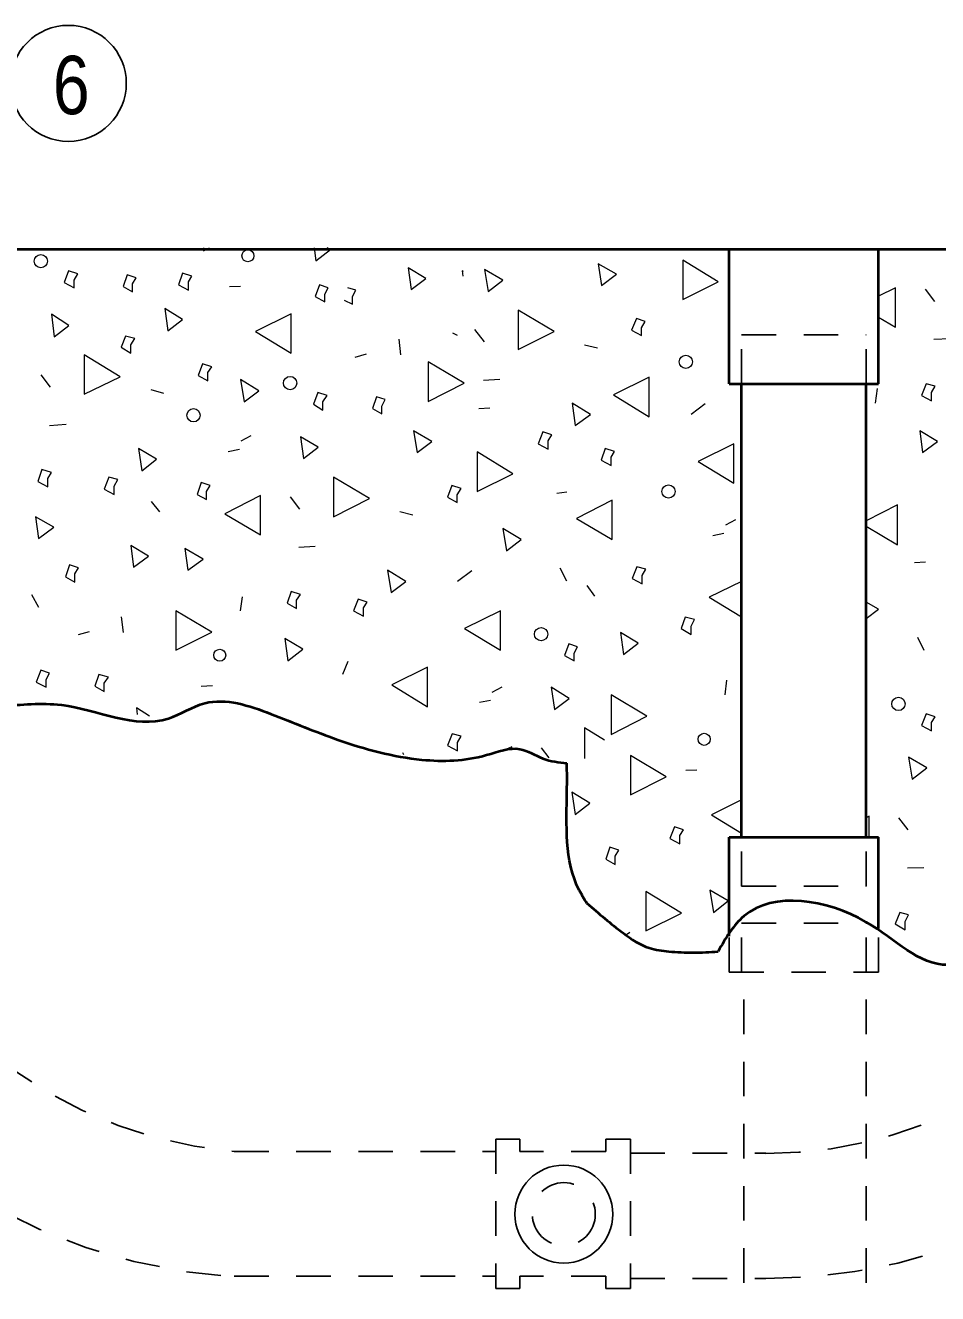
# Model space of a CAD drawing. Extents: x 312583 to 312854, y 144419 to 144597.
# Drawn here: x 312733.6 to 312745.49, y 144531.37 to 144547.9 of the extents above; entities that cross this region are included whole.
import ezdxf

# ---------------------------------------------------------------- set-up
doc = ezdxf.new("R2010")
doc.units = 0
doc.header["$LTSCALE"] = 0.3
doc.linetypes.add('SHORT_DASHED', pattern=[2.7, 1.5, -1.2])
doc.layers.add('1', color=7, linetype='Continuous', lineweight=25)
doc.layers.add('2', color=7, linetype='Continuous', lineweight=13)

msp = doc.modelspace()

# ---------------------------------------------------------------- linework, layer by layer
at = {"layer": '1', "lineweight": 40}
for p, q in [((312722.2688, 144544.9833), (312760.6021, 144544.9833)), ((312742.7771, 144543.2276), (312742.7771, 144544.9833)), ((312744.7245, 144543.2276), (312744.7245, 144544.9833)), ((312742.7771, 144543.2276), (312744.7245, 144543.2276)), ((312742.9381, 144537.3166), (312742.9381, 144543.2276)), ((312744.5635, 144537.3166), (312744.5635, 144543.2276)), ((312742.7771, 144537.3166), (312744.7245, 144537.3166)), ((312742.7771, 144536.0286), (312742.7771, 144537.3166)), ((312744.7245, 144536.1283), (312744.7245, 144537.3166))]:
    msp.add_line(p, q, dxfattribs=at)
at = {"layer": '1', "linetype": 'SHORT_DASHED'}
for p, q in [((312742.9381, 144543.8639), (312744.5635, 144543.8639)), ((312742.9381, 144543.2276), (312742.9381, 144543.8639)), ((312744.5635, 144543.2276), (312744.5635, 144543.8639)), ((312742.9381, 144536.6803), (312742.9381, 144537.3166)), ((312744.5635, 144536.6803), (312744.5635, 144537.3166)), ((312742.9381, 144536.6803), (312744.5635, 144536.6803)), ((312742.9381, 144536.1973), (312744.5635, 144536.1973)), ((312742.9381, 144535.5609), (312742.9381, 144536.1973)), ((312744.5635, 144535.5609), (312744.5635, 144536.1973)), ((312744.7245, 144535.5609), (312744.7245, 144536.1283)), ((312742.7771, 144535.5609), (312742.7771, 144536.0286)), ((312742.7771, 144535.5609), (312744.7245, 144535.5609)), ((312742.9688, 144524.2219), (312742.9688, 144535.5609)), ((312744.5635, 144524.2219), (312744.5635, 144535.5609)), ((312739.7335, 144533.3836), (312739.7335, 144531.4363)), ((312739.7335, 144533.3836), (312740.0478, 144533.3836)), ((312740.0478, 144533.3836), (312740.0478, 144533.2226)), ((312741.1671, 144533.3836), (312741.1671, 144533.2226)), ((312741.1671, 144533.3836), (312741.4891, 144533.3836)), ((312741.4891, 144533.3836), (312741.4891, 144531.4363)), ((312736.3218, 144533.2226), (312739.7335, 144533.2226)), ((312741.1671, 144533.2226), (312740.0478, 144533.2226)), ((312741.4891, 144533.1996), (312743.2525, 144533.1996)), ((312736.3218, 144531.5973), (312739.7335, 144531.5973)), ((312740.0478, 144531.4363), (312740.0478, 144531.5973)), ((312741.1671, 144531.5973), (312740.0478, 144531.5973)), ((312741.1671, 144531.4363), (312741.1671, 144531.5973)), ((312741.4891, 144531.5666), (312743.2525, 144531.5666)), ((312739.7335, 144531.4363), (312740.0478, 144531.4363)), ((312741.1671, 144531.4363), (312741.4891, 144531.4363))]:
    msp.add_line(p, q, dxfattribs=at)
at = {"layer": '1'}
msp.add_circle((312740.6202, 144532.4061), 0.6389, dxfattribs=at)
at = {"layer": '1', "linetype": 'SHORT_DASHED'}
msp.add_circle((312740.6202, 144532.4061), 0.4108, dxfattribs=at)
for centre, radius, start, end in [((312736.8038, 144538.9545), 5.75, 184.14986, 265.21724), ((312736.7767, 144538.9543), 7.3792, 186.13, 266.47596), ((312743.2557, 144538.9458), 5.75, 270, 336.76867), ((312743.2557, 144538.9458), 7.3792, 270, 340.7336)]:
    msp.add_arc(centre, radius, start, end, dxfattribs=at)
at = {"layer": '1', "lineweight": 40}
for points in [[(312755.0745, 144544.9833), (312755.5728, 144544.1169), (312756.1785, 144543.2276), (312755.8258, 144542.1543), (312755.2585, 144541.7173), (312755.0055, 144540.7973), (312754.8828, 144538.5893), (312754.3461, 144537.5159), (312754.1851, 144537.3243), (312753.2728, 144536.5346), (312752.7131, 144536.7646), (312751.8468, 144536.6649), (312751.0801, 144536.7263), (312750.2215, 144536.5116), (312749.1635, 144536.4733), (312748.5425, 144536.6803), (312747.8065, 144536.3813), (312747.7145, 144536.2816), (312747.0091, 144536.3889), (312745.9128, 144535.7143), (312745.6291, 144535.6529), (312744.5635, 144536.2126), (312742.9688, 144536.2893), (312742.6315, 144535.8293)], [(312732.0975, 144538.9879), (312733.2858, 144539.0263), (312734.0678, 144539.0416), (312735.4631, 144538.8653), (312735.9385, 144539.0646), (312736.7971, 144538.9266), (312737.6711, 144538.5893), (312738.7675, 144538.3286), (312739.6108, 144538.3899), (312740.0478, 144538.4666), (312740.3468, 144538.3439), (312740.6611, 144538.2826)], [(312740.9218, 144536.4579), (312740.8221, 144536.6266), (312740.6611, 144537.9223), (312740.6611, 144538.2826)], [(312740.9218, 144536.4579), (312741.3971, 144536.0669), (312741.7345, 144535.8753), (312741.9875, 144535.8293)], [(312741.9875, 144535.8293), (312742.3095, 144535.8139), (312742.6315, 144535.8293)]]:
    msp.add_spline(points, degree=3, dxfattribs=at)
at = {"layer": '2'}
for p, q in [((312737.3645, 144544.9986), (312737.3875, 144544.8299)), ((312736.2605, 144544.4926), (312736.4061, 144544.5003)), ((312745.3301, 144544.4619), (312745.4528, 144544.3009)), ((312744.7245, 144544.0939), (312744.9468, 144543.9636)), ((312739.2351, 144543.8563), (312739.1738, 144543.8869)), ((312739.4575, 144543.9329), (312739.5801, 144543.7719)), ((312738.4685, 144543.8103), (312738.4915, 144543.6033)), ((312740.8911, 144543.7336), (312741.0598, 144543.6953)), ((312745.4451, 144543.8103), (312745.6598, 144543.8179)), ((312737.9011, 144543.5726), (312738.0468, 144543.6186)), ((312733.7995, 144543.3426), (312733.9221, 144543.1816)), ((312739.5725, 144543.2736), (312739.7871, 144543.2889)), ((312735.2331, 144543.1509), (312735.4018, 144543.1049)), ((312744.6861, 144542.9746), (312744.7091, 144543.1663)), ((312739.5111, 144542.9056), (312739.6568, 144542.9133)), ((312742.4628, 144542.9669), (312742.2788, 144542.8289)), ((312733.9145, 144542.6833), (312734.1291, 144542.6986)), ((312736.4138, 144542.4839), (312736.5441, 144542.5529)), ((312736.2451, 144542.3459), (312736.3908, 144542.3766)), ((312735.2408, 144541.6943), (312735.3481, 144541.5563)), ((312737.0501, 144541.7556), (312737.1728, 144541.5946)), ((312740.5308, 144541.8016), (312740.6611, 144541.8169)), ((312738.4838, 144541.5639), (312738.6525, 144541.5179)), ((312742.7311, 144541.3876), (312742.8615, 144541.4566)), ((312744.5635, 144541.3723), (312744.9698, 144541.1269)), ((312742.5625, 144541.2496), (312742.7081, 144541.2803)), ((312737.1651, 144541.0963), (312737.3798, 144541.1116)), ((312745.1921, 144540.8969), (312745.3378, 144540.9046)), ((312739.4191, 144540.7896), (312739.2351, 144540.6516)), ((312740.5691, 144540.8279), (312740.6535, 144540.6593)), ((312740.9218, 144540.5979), (312741.0215, 144540.4599)), ((312733.6768, 144540.4829), (312733.7688, 144540.3143)), ((312736.4061, 144540.2683), (312736.4291, 144540.4523)), ((312734.8498, 144540.1916), (312734.8728, 144539.9846)), ((312734.2901, 144539.9616), (312734.4358, 144539.9999)), ((312745.2305, 144539.9233), (312745.3148, 144539.7546)), ((312737.8015, 144539.6089), (312737.7325, 144539.4403)), ((312735.8925, 144539.2869), (312736.0381, 144539.2946)), ((312739.6875, 144539.2103), (312739.8178, 144539.2793)), ((312742.7235, 144539.1719), (312742.7465, 144539.3636)), ((312739.5188, 144539.0799), (312739.6645, 144539.1029)), ((312740.8911, 144538.7426), (312740.8911, 144538.3439)), ((312741.1518, 144538.5816), (312740.8911, 144538.7426)), ((312738.5145, 144538.4206), (312738.5298, 144538.3976)), ((312740.3238, 144538.4819), (312740.4235, 144538.3516)), ((312742.2098, 144538.1906), (312742.3555, 144538.1983)), ((312744.9851, 144537.5696), (312745.1078, 144537.4163)), ((312745.1001, 144536.9179), (312745.3148, 144536.9256)), ((312741.4815, 144536.0746), (312741.4355, 144536.0439))]:
    msp.add_line(p, q, dxfattribs=at)
for points in [[(312735.9231, 144544.9986), (312735.9231, 144544.9603), (312735.9998, 144544.9986)], [(312737.3875, 144544.8299), (312737.5791, 144544.9756), (312737.5331, 144544.9986)], [(312739.3118, 144544.6919), (312739.2965, 144544.6996), (312739.3041, 144544.6306)], [(312737.7555, 144544.3163), (312737.8628, 144544.2626), (312737.8628, 144544.3623)], [(312737.8628, 144544.3623), (312737.9088, 144544.4466), (312737.8015, 144544.4773)], [(312744.9468, 144543.9636), (312744.9468, 144544.4773), (312744.7245, 144544.3699)], [(312744.9698, 144541.1269), (312744.9698, 144541.6483), (312744.5635, 144541.4413)], [(312742.9381, 144540.6516), (312742.5165, 144540.4446), (312742.9381, 144540.1916)], [(312744.5635, 144540.1686), (312744.7245, 144540.2913), (312744.5635, 144540.3833)], [(312735.2178, 144538.8959), (312735.0491, 144539.0033), (312735.0568, 144538.9189)], [(312739.9405, 144538.4513), (312739.9405, 144538.4973), (312739.8255, 144538.4436)], [(312742.9381, 144537.8073), (312742.5471, 144537.6079), (312742.9381, 144537.3703)], [(312744.6018, 144537.3166), (312744.6018, 144537.5926), (312744.5635, 144537.5696)]]:
    msp.add_lwpolyline(points, dxfattribs=at)
for points in [[(312742.1715, 144544.8376), (312742.1715, 144544.3239), (312742.6315, 144544.5539)], [(312734.2365, 144544.5769), (312734.2825, 144544.6613), (312734.1598, 144544.6996), (312734.1061, 144544.5463), (312734.2365, 144544.4773)], [(312735.7238, 144544.5539), (312735.7698, 144544.6306), (312735.6471, 144544.6689), (312735.5935, 144544.5156), (312735.7238, 144544.4466)], [(312738.6295, 144544.4543), (312738.8211, 144544.5999), (312738.5911, 144544.7379)], [(312739.6338, 144544.4313), (312739.8255, 144544.5769), (312739.5878, 144544.7149)], [(312741.1135, 144544.5079), (312741.3051, 144544.6536), (312741.0675, 144544.7916)], [(312734.9955, 144544.5309), (312735.0415, 144544.6076), (312734.9265, 144544.6459), (312734.8728, 144544.4926), (312734.9955, 144544.4236)], [(312737.5025, 144544.3929), (312737.5485, 144544.4773), (312737.4335, 144544.5156), (312737.3798, 144544.3623), (312737.5025, 144544.2933)], [(312735.4555, 144543.9176), (312735.6471, 144544.0633), (312735.4171, 144544.2089)], [(312740.0248, 144544.1859), (312740.0248, 144543.6723), (312740.4925, 144543.9099)], [(312733.9758, 144543.8409), (312734.1675, 144543.9866), (312733.9375, 144544.1323)], [(312737.0655, 144543.6263), (312737.0655, 144544.1399), (312736.5978, 144543.9099)], [(312741.6348, 144543.9559), (312741.6808, 144544.0403), (312741.5658, 144544.0786), (312741.5045, 144543.9253), (312741.6348, 144543.8563)], [(312734.9725, 144543.7336), (312735.0261, 144543.8179), (312734.9035, 144543.8486), (312734.8498, 144543.7029), (312734.9725, 144543.6263)], [(312734.3668, 144543.6033), (312734.3668, 144543.0896), (312734.8345, 144543.3196)], [(312738.8518, 144543.5113), (312738.8518, 144542.9976), (312739.3195, 144543.2353)], [(312735.9768, 144543.3733), (312736.0305, 144543.4499), (312735.9078, 144543.4883), (312735.8541, 144543.3349), (312735.9768, 144543.2659)], [(312736.4521, 144542.9899), (312736.6438, 144543.1356), (312736.4061, 144543.2813)], [(312741.7345, 144542.7983), (312741.7345, 144543.3119), (312741.2668, 144543.0819)], [(312745.4145, 144543.1126), (312745.4605, 144543.1969), (312745.3455, 144543.2276), (312745.2841, 144543.0743), (312745.4145, 144543.0053)], [(312737.4795, 144542.9899), (312737.5331, 144543.0743), (312737.4105, 144543.1126), (312737.3568, 144542.9593), (312737.4795, 144542.8826)], [(312738.2461, 144542.9363), (312738.2921, 144543.0206), (312738.1771, 144543.0589), (312738.1235, 144542.9056), (312738.2461, 144542.8366)], [(312740.7685, 144542.6833), (312740.9678, 144542.8289), (312740.7301, 144542.9746)], [(312737.2265, 144542.2539), (312737.4181, 144542.3996), (312737.1881, 144542.5376)], [(312738.7061, 144542.3306), (312738.8978, 144542.4763), (312738.6601, 144542.6143)], [(312740.4158, 144542.4839), (312740.4618, 144542.5606), (312740.3468, 144542.5989), (312740.2855, 144542.4456), (312740.4158, 144542.3766)], [(312745.2995, 144542.3306), (312745.4911, 144542.4763), (312745.2611, 144542.6143)], [(312735.1181, 144542.0929), (312735.3098, 144542.2463), (312735.0721, 144542.3843)], [(312741.2361, 144542.2693), (312741.2821, 144542.3459), (312741.1595, 144542.3843), (312741.1058, 144542.2309), (312741.2361, 144542.1619)], [(312742.8385, 144541.9319), (312742.8385, 144542.4456), (312742.3708, 144542.2156)], [(312739.4881, 144542.3383), (312739.4881, 144541.8246), (312739.9558, 144542.0546)], [(312733.8915, 144541.9933), (312733.9375, 144542.0699), (312733.8148, 144542.1083), (312733.7611, 144541.9549), (312733.8915, 144541.8859)], [(312734.7578, 144541.8936), (312734.8038, 144541.9779), (312734.6888, 144542.0086), (312734.6275, 144541.8553), (312734.7578, 144541.7863)], [(312735.9615, 144541.8246), (312736.0075, 144541.9013), (312735.8925, 144541.9396), (312735.8388, 144541.7863), (312735.9615, 144541.7173)], [(312737.6175, 144542.0086), (312737.6175, 144541.4949), (312738.0851, 144541.7326)], [(312739.2275, 144541.7786), (312739.2811, 144541.8629), (312739.1585, 144541.9013), (312739.1048, 144541.7479), (312739.2275, 144541.6789)], [(312736.6668, 144541.2573), (312736.6668, 144541.7709), (312736.1991, 144541.5333)], [(312741.2515, 144541.1959), (312741.2515, 144541.7096), (312740.7838, 144541.4719)], [(312733.7688, 144541.2113), (312733.9681, 144541.3569), (312733.7305, 144541.4949)], [(312739.8715, 144541.0503), (312740.0631, 144541.1959), (312739.8255, 144541.3416)], [(312735.0108, 144540.8356), (312735.2025, 144540.9813), (312734.9725, 144541.1193)], [(312735.7161, 144540.7973), (312735.9155, 144540.9429), (312735.6778, 144541.0809)], [(312734.2441, 144540.7513), (312734.2901, 144540.8279), (312734.1751, 144540.8663), (312734.1215, 144540.7129), (312734.2441, 144540.6439)], [(312738.3688, 144540.5059), (312738.5605, 144540.6516), (312738.3228, 144540.7973)], [(312741.6425, 144540.7283), (312741.6885, 144540.8126), (312741.5735, 144540.8433), (312741.5121, 144540.6899), (312741.6425, 144540.6209)], [(312737.1345, 144540.4063), (312737.1881, 144540.4829), (312737.0655, 144540.5213), (312737.0118, 144540.3679), (312737.1345, 144540.2989)], [(312738.0085, 144540.3066), (312738.0545, 144540.3833), (312737.9395, 144540.4216), (312737.8781, 144540.2683), (312738.0085, 144540.1993)], [(312735.5628, 144540.2683), (312735.5628, 144539.7546), (312736.0305, 144539.9923)], [(312739.7948, 144539.7546), (312739.7948, 144540.2683), (312739.3271, 144540.0383)], [(312742.2788, 144540.0689), (312742.3248, 144540.1533), (312742.2021, 144540.1839), (312742.1485, 144540.0383), (312742.2788, 144539.9616)], [(312737.0195, 144539.6166), (312737.2188, 144539.7699), (312736.9811, 144539.9079)], [(312741.3971, 144539.7009), (312741.5888, 144539.8466), (312741.3588, 144539.9846)], [(312740.7531, 144539.7163), (312740.7991, 144539.8006), (312740.6841, 144539.8389), (312740.6305, 144539.6856), (312740.7531, 144539.6166)], [(312733.8685, 144539.3713), (312733.9145, 144539.4556), (312733.7995, 144539.4939), (312733.7381, 144539.3406), (312733.8685, 144539.2716)], [(312734.6275, 144539.3253), (312734.6811, 144539.4019), (312734.5585, 144539.4403), (312734.5048, 144539.2869), (312734.6275, 144539.2179)], [(312738.8441, 144539.0186), (312738.8441, 144539.5323), (312738.3765, 144539.3023)], [(312740.5001, 144538.9803), (312740.6918, 144539.1259), (312740.4541, 144539.2716)], [(312741.2361, 144539.1719), (312741.2361, 144538.6583), (312741.7038, 144538.8959)], [(312745.4145, 144538.8116), (312745.4605, 144538.8883), (312745.3455, 144538.9266), (312745.2841, 144538.7733), (312745.4145, 144538.7043)], [(312739.2351, 144538.5509), (312739.2811, 144538.6353), (312739.1661, 144538.6659), (312739.1048, 144538.5126), (312739.2351, 144538.4436)], [(312741.4891, 144538.3823), (312741.4891, 144537.8686), (312741.9568, 144538.1063)], [(312745.1615, 144538.0756), (312745.3531, 144538.2213), (312745.1155, 144538.3593)], [(312740.7685, 144537.6156), (312740.9601, 144537.7613), (312740.7225, 144537.9069)], [(312742.1331, 144537.3396), (312742.1791, 144537.4163), (312742.0641, 144537.4546), (312742.0028, 144537.3013), (312742.1331, 144537.2323)], [(312741.2898, 144537.0713), (312741.3358, 144537.1479), (312741.2208, 144537.1863), (312741.1671, 144537.0329), (312741.2898, 144536.9639)], [(312741.6885, 144536.6113), (312741.6885, 144536.0976), (312742.1561, 144536.3276)], [(312742.5701, 144536.3353), (312742.7618, 144536.4886), (312742.5241, 144536.6266)], [(312745.0695, 144536.2203), (312745.1155, 144536.3046), (312745.0005, 144536.3353), (312744.9391, 144536.1896), (312745.0695, 144536.1129)]]:
    msp.add_lwpolyline(points, close=True, dxfattribs=at)
at = {"layer": '2', "lineweight": 25}
msp.add_circle((312734.1592, 144547.1421), 0.7557, dxfattribs=at)
at = {"layer": '2'}
for centre, radius in [((312733.8004, 144544.8249), 0.0865), ((312736.5002, 144544.8954), 0.0784), ((312742.2106, 144543.5128), 0.0865), ((312737.0508, 144543.2363), 0.0865), ((312735.7913, 144542.8166), 0.0865), ((312741.9851, 144541.8229), 0.0865), ((312740.3233, 144539.9637), 0.0865), ((312736.1332, 144539.6895), 0.0784), ((312744.9834, 144539.0548), 0.0865), ((312742.4507, 144538.5938), 0.0784)]:
    msp.add_circle(centre, radius, dxfattribs=at)

# ---------------------------------------------------------------- texts
at = {"layer": '2', "width": 0.85}
msp.add_text('6', height=0.76, dxfattribs=at).set_placement((312733.9567, 144546.7405))

doc.saveas('drawing.dxf')
